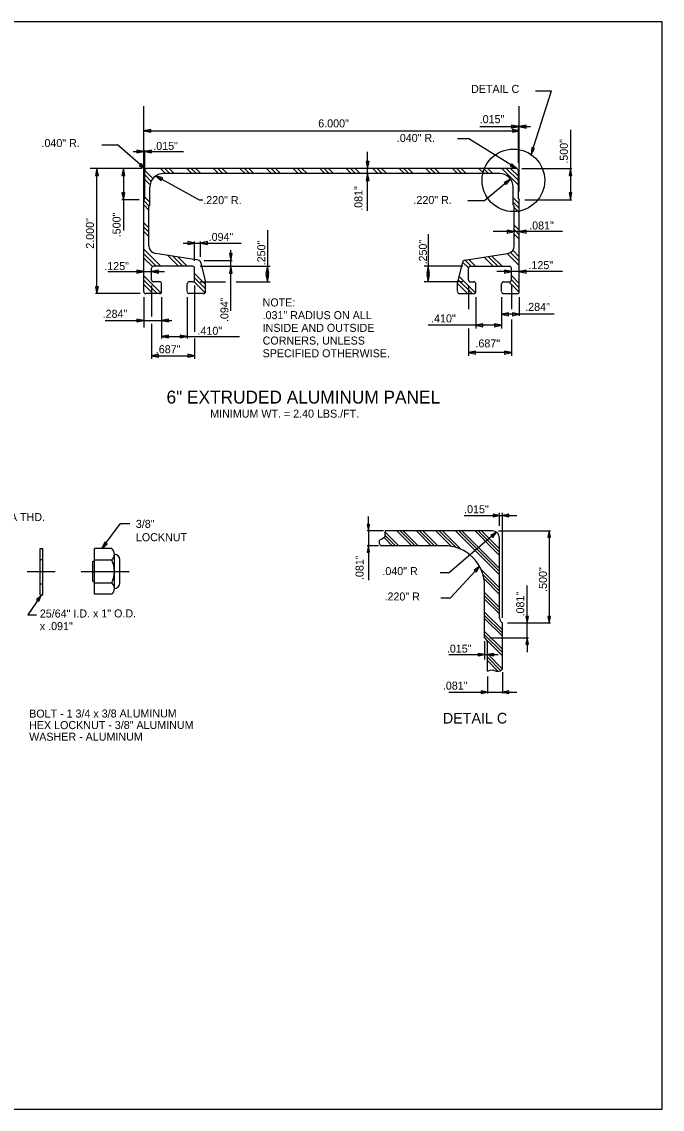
# Model space of a CAD drawing. Extents: x -439.1 to -407.9, y -458.1 to -437.7.
# Drawn here: x -419.86 to -407.86, y -458.05 to -437.68 of the extents above; entities that cross this region are included whole.
import ezdxf

# ---------------------------------------------------------------- set-up
doc = ezdxf.new("R2010")
doc.units = 0
for name, color, linetype in [('Draft_Named_Boundary', 7, 'Continuous'), ('Level 4', 7, 'Continuous'), ('Level 45', 7, 'Continuous')]:
    doc.layers.add(name, color=color, linetype=linetype)

msp = doc.modelspace()

# ---------------------------------------------------------------- linework, layer by layer
at = {"layer": 'Draft_Named_Boundary'}
msp.add_lwpolyline([(-439.109, -458.051), (-407.859, -458.051), (-407.859, -437.676), (-439.109, -437.676)], close=True, dxfattribs=at)
at = {"layer": 'Level 4'}
for p, q in [((-410.315, -440.165), (-409.935, -438.972)), ((-410.233, -438.972), (-409.935, -438.972)), ((-417.572, -441.017), (-417.572, -439.257)), ((-410.537, -440.855), (-410.537, -439.257)), ((-411.279, -439.641), (-410.328, -439.641)), ((-410.555, -440.322), (-410.555, -439.614)), ((-410.537, -440.024), (-410.537, -439.604)), ((-417.572, -439.72), (-410.537, -439.72)), ((-411.483, -439.87), (-411.693, -439.87)), ((-410.583, -440.428), (-411.483, -439.87)), ((-409.579, -439.7), (-409.579, -440.424)), ((-418.357, -439.984), (-418.063, -439.984)), ((-417.541, -440.439), (-418.063, -439.984)), ((-417.555, -440.431), (-417.555, -440.081)), ((-417.771, -440.107), (-416.828, -440.107)), ((-413.379, -441.218), (-413.379, -440.11)), ((-417.61, -440.424), (-418.575, -440.424)), ((-418.45, -442.769), (-418.45, -440.424)), ((-417.954, -440.424), (-417.954, -441.59)), ((-417.555, -440.98), (-417.555, -440.471)), ((-417.402, -440.615), (-417.554, -440.464)), ((-410.602, -440.424), (-417.508, -440.424)), ((-417.167, -440.519), (-417.262, -440.424)), ((-417.085, -440.519), (-417.179, -440.424)), ((-417.002, -440.519), (-417.096, -440.424)), ((-416.67, -440.519), (-416.764, -440.424)), ((-416.587, -440.519), (-416.682, -440.424)), ((-416.504, -440.519), (-416.599, -440.424)), ((-416.173, -440.519), (-416.267, -440.424)), ((-416.09, -440.519), (-416.184, -440.424)), ((-416.007, -440.519), (-416.101, -440.424)), ((-415.675, -440.519), (-415.77, -440.424)), ((-415.592, -440.519), (-415.687, -440.424)), ((-415.509, -440.519), (-415.604, -440.424)), ((-415.178, -440.519), (-415.272, -440.424)), ((-415.095, -440.519), (-415.189, -440.424)), ((-415.012, -440.519), (-415.106, -440.424)), ((-414.68, -440.519), (-414.775, -440.424)), ((-414.597, -440.519), (-414.692, -440.424)), ((-414.514, -440.519), (-414.609, -440.424)), ((-414.183, -440.519), (-414.277, -440.424)), ((-414.1, -440.519), (-414.194, -440.424)), ((-414.017, -440.519), (-414.112, -440.424)), ((-413.685, -440.519), (-413.78, -440.424)), ((-413.603, -440.519), (-413.697, -440.424)), ((-413.52, -440.519), (-413.614, -440.424)), ((-413.188, -440.519), (-413.282, -440.424)), ((-413.105, -440.519), (-413.2, -440.424)), ((-413.022, -440.519), (-413.117, -440.424)), ((-412.691, -440.519), (-412.785, -440.424)), ((-412.608, -440.519), (-412.702, -440.424)), ((-412.525, -440.519), (-412.619, -440.424)), ((-412.193, -440.519), (-412.288, -440.424)), ((-412.11, -440.519), (-412.205, -440.424)), ((-412.027, -440.519), (-412.122, -440.424)), ((-411.696, -440.519), (-411.79, -440.424)), ((-411.613, -440.519), (-411.707, -440.424)), ((-411.53, -440.519), (-411.624, -440.424)), ((-411.198, -440.519), (-411.293, -440.424)), ((-411.115, -440.519), (-411.21, -440.424)), ((-411.032, -440.519), (-411.127, -440.424)), ((-410.555, -440.735), (-410.866, -440.424)), ((-410.555, -440.652), (-410.783, -440.424)), ((-410.555, -440.57), (-410.7, -440.424)), ((-410.555, -440.98), (-410.555, -440.471)), ((-410.491, -440.424), (-409.552, -440.424)), ((-409.579, -440.424), (-409.579, -441.011)), ((-417.434, -440.666), (-417.555, -440.546)), ((-417.455, -440.729), (-417.555, -440.629)), ((-417.345, -440.563), (-416.536, -441.013)), ((-410.903, -440.519), (-417.202, -440.519)), ((-410.701, -440.624), (-411.182, -441.022)), ((-417.46, -441.105), (-417.46, -440.777)), ((-410.65, -441.105), (-410.65, -440.777)), ((-417.657, -441.011), (-417.981, -441.011)), ((-417.572, -442.732), (-417.572, -441.01)), ((-417.475, -441.124), (-417.572, -441.026)), ((-417.477, -441.204), (-417.572, -441.109)), ((-417.46, -441.056), (-417.555, -440.961)), ((-416.536, -441.013), (-416.463, -441.013)), ((-411.5, -441.022), (-411.182, -441.022)), ((-410.538, -441.085), (-410.65, -440.972)), ((-410.538, -441.167), (-410.65, -441.055)), ((-410.538, -442.732), (-410.538, -441.01)), ((-410.435, -441.011), (-409.552, -441.011)), ((-417.477, -441.874), (-417.477, -441.137)), ((-410.633, -441.874), (-410.633, -441.137)), ((-410.538, -441.25), (-410.633, -441.155)), ((-417.477, -441.536), (-417.572, -441.441)), ((-417.477, -441.618), (-417.572, -441.524)), ((-410.538, -441.582), (-410.633, -441.487)), ((-417.477, -441.701), (-417.572, -441.606)), ((-415.257, -441.579), (-415.257, -442.549)), ((-412.245, -441.653), (-412.245, -442.256)), ((-409.73, -441.607), (-411.027, -441.607)), ((-410.538, -441.665), (-410.633, -441.57)), ((-410.538, -441.748), (-410.633, -441.653)), ((-416.834, -441.823), (-415.748, -441.823)), ((-416.62, -442.153), (-416.62, -441.796)), ((-416.51, -442.079), (-416.51, -441.796)), ((-417.255, -442.255), (-417.572, -441.938)), ((-417.338, -442.255), (-417.572, -442.021)), ((-417.412, -442.264), (-417.572, -442.104)), ((-416.546, -442.145), (-417.353, -442.018)), ((-416.923, -442.255), (-417.124, -442.055)), ((-416.84, -442.255), (-417.026, -442.07)), ((-416.758, -442.255), (-416.927, -442.086)), ((-415.941, -443.095), (-415.941, -441.955)), ((-411.563, -442.145), (-410.756, -442.018)), ((-411.357, -442.255), (-411.48, -442.132)), ((-411.025, -442.255), (-411.193, -442.087)), ((-410.942, -442.255), (-411.122, -442.076)), ((-410.859, -442.255), (-411.05, -442.065)), ((-410.538, -442.245), (-410.763, -442.02)), ((-410.538, -442.162), (-410.702, -441.998)), ((-410.538, -442.079), (-410.659, -441.958)), ((-417.426, -442.512), (-417.426, -442.292)), ((-416.657, -442.255), (-417.389, -442.255)), ((-416.62, -442.512), (-416.62, -442.292)), ((-416.517, -442.256), (-415.205, -442.256)), ((-416.51, -442.181), (-416.416, -442.548)), ((-416.444, -442.146), (-415.914, -442.146)), ((-411.592, -442.256), (-412.319, -442.256)), ((-412.245, -442.256), (-412.245, -442.549)), ((-411.6, -442.181), (-411.694, -442.548)), ((-411.49, -442.288), (-411.599, -442.179)), ((-411.44, -442.255), (-411.552, -442.143)), ((-411.49, -442.512), (-411.49, -442.292)), ((-411.453, -442.255), (-410.72, -442.255)), ((-410.684, -442.512), (-410.684, -442.292)), ((-418.247, -442.358), (-417.184, -442.358)), ((-417.249, -442.758), (-417.572, -442.435)), ((-417.322, -442.769), (-417.572, -442.518)), ((-416.424, -442.755), (-416.636, -442.543)), ((-416.416, -442.597), (-416.62, -442.393)), ((-416.416, -442.68), (-416.62, -442.476)), ((-411.423, -442.769), (-411.683, -442.509)), ((-411.357, -442.752), (-411.667, -442.443)), ((-409.73, -442.358), (-410.955, -442.358)), ((-410.538, -442.577), (-410.684, -442.43)), ((-410.538, -442.66), (-410.684, -442.513)), ((-417.405, -442.769), (-417.572, -442.601)), ((-417.426, -442.615), (-417.426, -443.199)), ((-417.276, -442.548), (-417.389, -442.548)), ((-417.239, -442.732), (-417.239, -442.585)), ((-416.759, -442.732), (-416.759, -442.585)), ((-416.657, -442.548), (-416.722, -442.548)), ((-416.62, -442.615), (-416.62, -443.484)), ((-416.517, -442.549), (-416.039, -442.549)), ((-416.416, -442.732), (-416.416, -442.548)), ((-415.844, -442.549), (-415.205, -442.549)), ((-411.592, -442.549), (-412.319, -442.549)), ((-411.694, -442.732), (-411.694, -442.548)), ((-411.506, -442.769), (-411.694, -442.582)), ((-411.49, -442.615), (-411.49, -443.063)), ((-411.453, -442.548), (-411.388, -442.548)), ((-411.351, -442.732), (-411.351, -442.585)), ((-410.871, -442.732), (-410.871, -442.585)), ((-410.834, -442.548), (-410.72, -442.548)), ((-410.539, -442.742), (-410.732, -442.548)), ((-410.684, -442.615), (-410.684, -443.063)), ((-417.638, -442.769), (-418.477, -442.769)), ((-417.572, -442.836), (-417.572, -443.403)), ((-417.276, -442.769), (-417.536, -442.769)), ((-417.239, -442.836), (-417.239, -443.613)), ((-416.758, -442.836), (-416.758, -443.613)), ((-416.453, -442.769), (-416.722, -442.769)), ((-411.657, -442.769), (-411.388, -442.769)), ((-411.351, -442.836), (-411.351, -443.42)), ((-410.87, -442.836), (-410.87, -443.42)), ((-410.834, -442.769), (-410.574, -442.769)), ((-410.537, -442.836), (-410.537, -443.188)), ((-418.293, -443.274), (-417.044, -443.274)), ((-417.426, -443.337), (-417.426, -443.989)), ((-410.537, -443.157), (-410.87, -443.157)), ((-410.684, -443.254), (-410.684, -443.933)), ((-409.883, -443.157), (-410.537, -443.157)), ((-411.351, -443.363), (-412.243, -443.363)), ((-411.49, -443.42), (-411.49, -443.933)), ((-410.87, -443.363), (-411.351, -443.363)), ((-417.239, -443.572), (-415.782, -443.572)), ((-416.62, -443.613), (-416.62, -443.989)), ((-417.426, -443.933), (-416.62, -443.933)), ((-410.684, -443.874), (-411.49, -443.874)), ((-413.365, -447.213), (-413.365, -446.943)), ((-411.571, -446.924), (-410.907, -446.924)), ((-410.907, -447.118), (-410.907, -446.876)), ((-410.907, -446.924), (-410.855, -446.924)), ((-410.855, -448.845), (-410.855, -446.876)), ((-410.855, -446.924), (-410.585, -446.924)), ((-418.359, -447.546), (-418.01, -447.079)), ((-418.01, -447.079), (-417.833, -447.079)), ((-413.082, -447.213), (-413.39, -447.213)), ((-413.365, -447.213), (-413.365, -447.493)), ((-411.041, -447.213), (-413.047, -447.213)), ((-412.832, -447.213), (-412.552, -447.493)), ((-412.771, -447.213), (-412.491, -447.493)), ((-412.71, -447.213), (-412.43, -447.493)), ((-412.465, -447.213), (-412.186, -447.493)), ((-412.404, -447.213), (-412.125, -447.493)), ((-412.343, -447.213), (-412.064, -447.493)), ((-412.099, -447.213), (-411.807, -447.505)), ((-412.038, -447.213), (-411.723, -447.528)), ((-411.977, -447.213), (-411.625, -447.564)), ((-411.733, -447.213), (-410.907, -448.039)), ((-411.672, -447.213), (-410.907, -447.978)), ((-411.611, -447.213), (-410.907, -447.917)), ((-411.367, -447.213), (-410.907, -447.673)), ((-411.305, -447.213), (-410.907, -447.612)), ((-411.244, -447.213), (-410.907, -447.551)), ((-410.924, -447.213), (-409.953, -447.213)), ((-409.978, -447.213), (-409.978, -448.94)), ((-413.07, -447.341), (-412.918, -447.493)), ((-413.058, -447.292), (-412.857, -447.493)), ((-413.052, -447.237), (-412.796, -447.493)), ((-410.962, -447.24), (-411.842, -447.995)), ((-410.906, -448.843), (-410.906, -447.351)), ((-419.516, -448.41), (-419.516, -447.546)), ((-419.516, -447.546), (-419.465, -447.546)), ((-419.465, -448.41), (-419.465, -447.546)), ((-418.496, -448.403), (-418.496, -447.546)), ((-418.172, -447.546), (-418.496, -447.546)), ((-413.176, -447.493), (-413.39, -447.493)), ((-413.365, -447.493), (-413.365, -448.136)), ((-411.946, -447.492), (-413.14, -447.492)), ((-419.516, -447.754), (-419.465, -447.754)), ((-418.525, -448.165), (-418.525, -447.785)), ((-418.522, -447.785), (-418.496, -447.785)), ((-418.496, -447.76), (-418.172, -447.76)), ((-418.121, -448.296), (-418.121, -447.653)), ((-418.02, -448.195), (-418.02, -447.755)), ((-419.756, -447.978), (-419.234, -447.978)), ((-418.747, -447.975), (-417.844, -447.975)), ((-412.021, -447.995), (-411.842, -447.995)), ((-411.282, -447.883), (-411.829, -448.471)), ((-411.258, -447.932), (-410.907, -448.283)), ((-411.222, -448.029), (-410.907, -448.344)), ((-419.516, -448.204), (-419.465, -448.204)), ((-418.522, -448.165), (-418.496, -448.165)), ((-418.496, -448.189), (-418.172, -448.189)), ((-411.198, -448.114), (-410.907, -448.405)), ((-410.389, -448.94), (-410.389, -448.24)), ((-419.491, -448.41), (-419.745, -448.786)), ((-419.516, -448.41), (-419.465, -448.41)), ((-418.172, -448.403), (-418.496, -448.403)), ((-411.186, -449.219), (-411.186, -448.252)), ((-411.186, -448.37), (-410.907, -448.65)), ((-411.186, -448.431), (-410.907, -448.711)), ((-412.008, -448.471), (-411.829, -448.471)), ((-411.186, -448.492), (-410.907, -448.772)), ((-419.745, -448.786), (-419.58, -448.786)), ((-411.186, -448.736), (-410.855, -449.068)), ((-411.186, -448.797), (-410.855, -449.129)), ((-411.186, -448.858), (-410.855, -449.19)), ((-410.855, -449.799), (-410.855, -448.94)), ((-410.76, -448.94), (-409.953, -448.94)), ((-410.389, -449.219), (-410.389, -448.94)), ((-411.186, -449.102), (-410.855, -449.434)), ((-411.186, -449.164), (-410.855, -449.495)), ((-411.146, -449.265), (-410.855, -449.556)), ((-411.092, -449.219), (-410.365, -449.219)), ((-410.389, -449.219), (-410.389, -449.489)), ((-411.186, -449.281), (-411.186, -449.623)), ((-411.134, -449.844), (-411.134, -449.306)), ((-411.855, -449.533), (-411.186, -449.533)), ((-411.186, -449.533), (-411.135, -449.533)), ((-411.135, -449.533), (-410.933, -449.533)), ((-411.134, -449.521), (-410.856, -449.8)), ((-411.134, -449.582), (-410.888, -449.828)), ((-411.134, -449.643), (-410.93, -449.847)), ((-410.855, -449.864), (-410.855, -450.264)), ((-411.135, -449.943), (-411.135, -450.264)), ((-411.855, -450.239), (-411.135, -450.239)), ((-411.135, -450.239), (-410.855, -450.239)), ((-410.855, -450.239), (-410.585, -450.239))]:
    msp.add_line(p, q, dxfattribs=at)
for points in [[(-410.685, -439.668), (-410.555, -439.641), (-410.685, -439.614)], [(-410.408, -439.614), (-410.537, -439.641), (-410.408, -439.668)], [(-417.442, -439.693), (-417.572, -439.72), (-417.442, -439.746)], [(-410.667, -439.746), (-410.537, -439.72), (-410.667, -439.693)], [(-417.702, -440.134), (-417.572, -440.107), (-417.702, -440.081)], [(-417.425, -440.081), (-417.555, -440.107), (-417.425, -440.134)], [(-410.301, -440.033), (-410.315, -440.165), (-410.25, -440.049)], [(-413.406, -440.295), (-413.379, -440.424), (-413.352, -440.295)], [(-418.423, -440.554), (-418.45, -440.424), (-418.477, -440.554)], [(-417.927, -440.554), (-417.954, -440.424), (-417.981, -440.554)], [(-417.657, -440.374), (-417.541, -440.439), (-417.621, -440.333)], [(-410.708, -440.383), (-410.583, -440.428), (-410.68, -440.337)], [(-409.552, -440.554), (-409.579, -440.424), (-409.606, -440.554)], [(-417.218, -440.602), (-417.345, -440.563), (-417.244, -440.649)], [(-413.352, -440.649), (-413.379, -440.519), (-413.406, -440.649)], [(-410.783, -440.727), (-410.701, -440.624), (-410.818, -440.686)], [(-417.981, -440.881), (-417.954, -441.011), (-417.927, -440.881)], [(-409.606, -440.881), (-409.579, -441.011), (-409.552, -440.881)], [(-410.762, -441.634), (-410.632, -441.607), (-410.762, -441.58)], [(-410.408, -441.58), (-410.537, -441.607), (-410.408, -441.634)], [(-416.75, -441.85), (-416.62, -441.823), (-416.75, -441.796)], [(-416.38, -441.796), (-416.51, -441.823), (-416.38, -441.85)], [(-415.968, -442.016), (-415.941, -442.146), (-415.914, -442.016)], [(-417.702, -442.385), (-417.572, -442.358), (-417.702, -442.331)], [(-417.296, -442.331), (-417.426, -442.358), (-417.296, -442.385)], [(-415.914, -442.385), (-415.941, -442.256), (-415.968, -442.385)], [(-415.231, -442.385), (-415.257, -442.256), (-415.284, -442.385)], [(-412.218, -442.385), (-412.245, -442.256), (-412.272, -442.385)], [(-410.814, -442.385), (-410.684, -442.358), (-410.814, -442.331)], [(-410.408, -442.331), (-410.537, -442.358), (-410.408, -442.385)], [(-415.284, -442.419), (-415.257, -442.549), (-415.231, -442.419)], [(-412.272, -442.419), (-412.245, -442.549), (-412.218, -442.419)], [(-418.477, -442.64), (-418.45, -442.769), (-418.423, -442.64)], [(-410.741, -443.13), (-410.87, -443.157), (-410.741, -443.184)], [(-410.667, -443.184), (-410.537, -443.157), (-410.667, -443.13)], [(-417.702, -443.301), (-417.572, -443.274), (-417.702, -443.247)], [(-417.109, -443.247), (-417.239, -443.274), (-417.109, -443.301)], [(-411.221, -443.336), (-411.351, -443.363), (-411.221, -443.39)], [(-411, -443.39), (-410.87, -443.363), (-411, -443.336)], [(-417.109, -443.545), (-417.239, -443.572), (-417.109, -443.599)], [(-416.888, -443.599), (-416.758, -443.572), (-416.888, -443.545)], [(-417.296, -443.906), (-417.426, -443.933), (-417.296, -443.96)], [(-416.75, -443.96), (-416.62, -443.933), (-416.75, -443.906)], [(-411.36, -443.848), (-411.49, -443.874), (-411.36, -443.901)], [(-410.814, -443.901), (-410.684, -443.874), (-410.814, -443.848)], [(-411.026, -446.949), (-410.907, -446.924), (-411.026, -446.899)], [(-410.735, -446.899), (-410.855, -446.924), (-410.735, -446.949)], [(-413.39, -447.093), (-413.365, -447.213), (-413.341, -447.093)], [(-409.953, -447.332), (-409.978, -447.213), (-410.003, -447.332)], [(-418.304, -447.428), (-418.359, -447.546), (-418.261, -447.46)], [(-411.036, -447.337), (-410.962, -447.24), (-411.069, -447.299)], [(-413.341, -447.612), (-413.365, -447.493), (-413.39, -447.612)], [(-411.346, -447.987), (-411.282, -447.883), (-411.382, -447.953)], [(-419.54, -448.53), (-419.491, -448.41), (-419.584, -448.501)], [(-410.414, -448.82), (-410.389, -448.94), (-410.365, -448.82)], [(-410.003, -448.82), (-409.978, -448.94), (-409.953, -448.82)], [(-410.365, -449.339), (-410.389, -449.219), (-410.414, -449.339)], [(-411.306, -449.558), (-411.186, -449.533), (-411.306, -449.509)], [(-411.015, -449.509), (-411.135, -449.533), (-411.015, -449.558)], [(-411.254, -450.264), (-411.135, -450.239), (-411.254, -450.214)], [(-410.735, -450.214), (-410.855, -450.239), (-410.735, -450.264)]]:
    msp.add_lwpolyline(points, close=True, dxfattribs=at)
for points in [[(-413.047, -447.213), (-413.056, -447.244), (-413.059, -447.276), (-413.057, -447.304), (-413.059, -447.329), (-413.079, -447.351), (-413.111, -447.367), (-413.144, -447.382), (-413.165, -447.403), (-413.163, -447.447), (-413.14, -447.492)], [(-411.134, -449.844), (-411.085, -449.823), (-411.033, -449.819), (-410.991, -449.837), (-410.949, -449.851), (-410.898, -449.836), (-410.855, -449.799)]]:
    msp.add_lwpolyline(points, dxfattribs=at)
msp.add_circle((-410.647, -440.648), 0.586, dxfattribs=at)
for centre, radius, start, end in [((-417.508, -440.471), 0.0469, 90, 180), ((-410.602, -440.471), 0.0469, 0, 90), ((-417.202, -440.777), 0.258, 90, 180), ((-410.908, -440.777), 0.258, 0, 90), ((-417.591, -440.979), 0.0363, 301, 2.7101), ((-417.441, -441.137), 0.0363, 120.983, 177.0065), ((-410.669, -441.137), 0.0363, 2.9935, 59), ((-410.519, -440.979), 0.0363, 177.2899, 239), ((-417.331, -441.874), 0.147, 180, 261.0533), ((-410.779, -441.874), 0.147, 278.9467, 360), ((-417.389, -442.292), 0.0363, 90, 180), ((-416.656, -442.292), 0.0363, 0, 90), ((-416.546, -442.182), 0.0363, 0, 90), ((-411.563, -442.182), 0.0363, 90, 180), ((-411.453, -442.292), 0.0363, 90, 180), ((-410.72, -442.292), 0.0363, 0, 90), ((-417.389, -442.513), 0.0363, 180, 270), ((-416.656, -442.513), 0.0363, 270, 360), ((-411.453, -442.513), 0.0363, 180, 270), ((-410.72, -442.513), 0.0363, 270, 0), ((-417.536, -442.733), 0.0363, 180, 270), ((-417.275, -442.585), 0.0363, 0, 90), ((-417.275, -442.733), 0.0363, 270, 360), ((-416.722, -442.585), 0.0363, 90, 180), ((-416.722, -442.733), 0.0363, 180, 270), ((-416.452, -442.733), 0.0363, 270, 360), ((-411.657, -442.733), 0.0363, 180, 270), ((-411.388, -442.585), 0.0363, 0, 90), ((-411.388, -442.733), 0.0363, 270, 0), ((-410.834, -442.585), 0.0363, 90, 180), ((-410.834, -442.733), 0.0363, 180, 270), ((-410.574, -442.733), 0.0363, 270, 0), ((-411.045, -447.351), 0.138, 0, 90), ((-418.259, -447.654), 0.138, 0, 50.6841), ((-411.946, -448.252), 0.76, 0, 90), ((-418.259, -447.654), 0.138, 309.3159, 0), ((-418.598, -447.975), 0.477, 333.3557, 26.6443), ((-418.121, -447.755), 0.101, 0, 90), ((-418.259, -448.296), 0.138, 0, 50.6841), ((-418.121, -448.194), 0.101, 270, 0), ((-418.259, -448.296), 0.138, 309.3159, 0), ((-410.8, -448.848), 0.107, 177.2899, 239), ((-411.242, -449.311), 0.107, 2.9935, 59)]:
    msp.add_arc(centre, radius, start, end, dxfattribs=at)

# ---------------------------------------------------------------- texts
for height, p in [(0.15, (-411.441, -439.009)), (0.2, (-411.968, -450.824))]:
    msp.add_text('DETAIL C', height=height, dxfattribs=at).set_placement(p)
at = {"layer": 'Level 45'}
for s, height, p in [('.015"', 0.15, (-411.279, -439.576)), ('6.000"', 0.15, (-414.304, -439.655)), ('.040" R.', 0.15, (-419.489, -440.023)), ('.040" R.', 0.15, (-412.832, -439.928)), ('.015"', 0.15, (-417.395, -440.077)), ('.220" R.', 0.15, (-416.458, -441.093)), ('.220" R.', 0.15, (-412.52, -441.09)), ('.081"', 0.15, (-410.352, -441.568)), ('.094"', 0.15, (-416.357, -441.782)), ('.125"', 0.15, (-418.312, -442.329)), ('.125"', 0.15, (-410.365, -442.311)), ('NOTE:', 0.15, (-415.346, -443.01)), ('.284"', 0.15, (-410.426, -443.093)), ('.284"', 0.15, (-418.343, -443.223)), ('.031" RADIUS ON ALL', 0.15, (-415.346, -443.248)), ('INSIDE AND OUTSIDE', 0.15, (-415.346, -443.486)), ('.410"', 0.15, (-412.189, -443.309)), ('.410"', 0.15, (-416.566, -443.541)), ('.687"', 0.15, (-417.347, -443.886)), ('CORNERS, UNLESS', 0.15, (-415.346, -443.724)), ('.687"', 0.15, (-411.359, -443.777)), ('SPECIFIED OTHERWISE.', 0.15, (-415.346, -443.962)), ('6" EXTRUDED ALUMINUM PANEL', 0.24167, (-417.146, -444.829)), ('MINIMUM WT. = 2.40 LBS./FT.', 0.15, (-416.328, -445.093)), ('.015"', 0.15, (-411.571, -446.884)), ('.040" R', 0.15, (-413.102, -448.043)), ('.220" R', 0.15, (-413.062, -448.519)), ('.015"', 0.15, (-411.894, -449.496)), ('.081"', 0.15, (-411.969, -450.189))]:
    msp.add_text(s, height=height, dxfattribs=at).set_placement(p)
for s, rotation, p in [('.500"', 90, (-409.628, -440.335)), ('.081"', 90, (-413.476, -441.218)), ('.500"', 90, (-418.007, -441.714)), ('2.000"', 90, (-418.507, -441.928)), ('.250"', 90, (-415.296, -442.239)), ('.250"', 90, (-412.269, -442.223)), ('.094"', 90, (-415.987, -443.302)), ('3/8" - 16 U.N.C. 2A THD.', 0.1, (-421.656, -447.034)), ('3/8" ', 0.1, (-417.721, -447.159)), ('LOCKNUT', 0.1, (-417.72, -447.409)), ('.081"', 90, (-413.455, -448.136)), ('.500"', 90, (-410.021, -448.357)), ('.081"', 90, (-410.445, -448.818)), ('25/64" I.D. x 1" O.D. ', 0.1, (-419.52, -448.839)), ('x .091"', 0.1, (-419.52, -449.075)), ('BOLT - 1 3/4 x 3/8 ALUMINUM', 0.1, (-419.72, -450.714)), ('HEX LOCKNUT - 3/8" ALUMINUM', 0.1, (-419.72, -450.93)), ('WASHER - ALUMINUM', 0.1, (-419.72, -451.147))]:
    msp.add_text(s, height=0.15, rotation=rotation, dxfattribs=at).set_placement(p)

doc.saveas('drawing.dxf')
